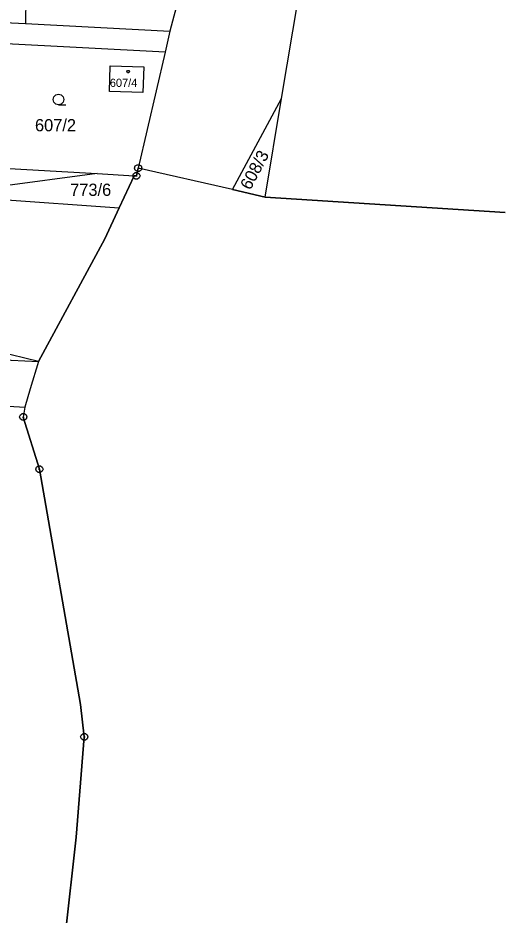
# Model space of a CAD drawing. Extents: x -759699 to -757730, y -1172308 to -1170857.
# Drawn here: x -758926.3 to -758859.4, y -1171766.9 to -1171642.4 of the extents above; entities that cross this region are included whole.
import ezdxf

# ---------------------------------------------------------------- set-up
doc = ezdxf.new("R2010")
doc.units = 0
for name, color, linetype in [('Vrstva 1', 7, 'Continuous'), ('Vrstva 11', 7, 'Continuous'), ('Vrstva 12', 7, 'Continuous'), ('Vrstva 2', 7, 'Continuous'), ('Vrstva 3', 7, 'Continuous'), ('Vrstva 5', 7, 'Continuous'), ('Vrstva 8', 7, 'Continuous')]:
    doc.layers.add(name, color=color, linetype=linetype)

msp = doc.modelspace()

# ---------------------------------------------------------------- linework, layer by layer
at = {"layer": 'Vrstva 1'}
for p, q in [((-758924.94, -1171622.09), (-758925.22, -1171643.14)), ((-758889.72, -1171653.54), (-758885.19, -1171626.24)), ((-758901.34, -1171629.35), (-758905.21, -1171644.2)), ((-758947.23, -1171641.98), (-758925.22, -1171643.14)), ((-758925.22, -1171643.14), (-758905.21, -1171644.2)), ((-758905.21, -1171644.2), (-758905.89, -1171647.12)), ((-758905.89, -1171647.12), (-758928.84, -1171645.89)), ((-758905.89, -1171647.12), (-758909.6, -1171663.2)), ((-758913.58, -1171652.56), (-758913.48, -1171648.99)), ((-758913.48, -1171648.99), (-758908.84, -1171649.12)), ((-758908.84, -1171649.12), (-758908.95, -1171652.69)), ((-758908.95, -1171652.69), (-758913.58, -1171652.56)), ((-758896.55, -1171666.17), (-758889.72, -1171653.54)), ((-758891.99, -1171667.21), (-758889.72, -1171653.54)), ((-758915.3, -1171663.96), (-758930.07, -1171665.92)), ((-758929.9, -1171663.12), (-758915.3, -1171663.96)), ((-758915.3, -1171663.96), (-758910.16, -1171664.25)), ((-758912.26, -1171668.73), (-758910.16, -1171664.25)), ((-758910.16, -1171664.25), (-758909.85, -1171664.27)), ((-758909.85, -1171664.27), (-758909.6, -1171663.2)), ((-758896.55, -1171666.17), (-758909.6, -1171663.2)), ((-758896.55, -1171666.17), (-758891.99, -1171667.21)), ((-758937.4, -1171666.9), (-758912.26, -1171668.73)), ((-758891.99, -1171667.21), (-758858.7, -1171669.36)), ((-758914.25, -1171672.99), (-758912.26, -1171668.73)), ((-758923.44, -1171690.05), (-758914.25, -1171672.99)), ((-758923.44, -1171690.05), (-758946.52, -1171684.31)), ((-759070.89, -1171687.29), (-758925.35, -1171696.39)), ((-758948.82, -1171688.7), (-758923.44, -1171690.05)), ((-758923.44, -1171690.05), (-758924.57, -1171693.81)), ((-758924.57, -1171693.81), (-758925.35, -1171696.39)), ((-758925.35, -1171696.39), (-758925.54, -1171697.74)), ((-758923.31, -1171704.98), (-758925.54, -1171697.74)), ((-758917.62, -1171737.66), (-758923.31, -1171704.98)), ((-758917.08, -1171742.13), (-758917.62, -1171737.66)), ((-758918.22, -1171756.06), (-758917.08, -1171742.13)), ((-758920.09, -1171772.69), (-758918.22, -1171756.06))]:
    msp.add_line(p, q, dxfattribs=at)
at = {"layer": 'Vrstva 11'}
for p, q in [((-758910.16, -1171664.25), (-758912.26, -1171668.73)), ((-758909.85, -1171664.27), (-758910.16, -1171664.25)), ((-758909.6, -1171663.2), (-758909.85, -1171664.27)), ((-758896.55, -1171666.17), (-758909.6, -1171663.2)), ((-758891.99, -1171667.21), (-758896.55, -1171666.17)), ((-758858.7, -1171669.36), (-758891.99, -1171667.21)), ((-758912.26, -1171668.73), (-758914.25, -1171672.99)), ((-758914.25, -1171672.99), (-758923.44, -1171690.05)), ((-758923.44, -1171690.05), (-758924.57, -1171693.81)), ((-758924.57, -1171693.81), (-758925.35, -1171696.39)), ((-758925.35, -1171696.39), (-758925.54, -1171697.74)), ((-758925.54, -1171697.74), (-758923.31, -1171704.98)), ((-758923.31, -1171704.98), (-758917.62, -1171737.66)), ((-758917.62, -1171737.66), (-758917.08, -1171742.13)), ((-758917.08, -1171742.13), (-758918.22, -1171756.06)), ((-758918.22, -1171756.06), (-758920.09, -1171772.69))]:
    msp.add_line(p, q, dxfattribs=at)
at = {"layer": 'Vrstva 12'}
for p, q in [((-758913.58, -1171652.56), (-758913.48, -1171648.99)), ((-758913.48, -1171648.99), (-758908.84, -1171649.12)), ((-758908.84, -1171649.12), (-758908.95, -1171652.69)), ((-758908.95, -1171652.69), (-758913.58, -1171652.56))]:
    msp.add_line(p, q, dxfattribs=at)
at = {"layer": 'Vrstva 3'}
msp.add_lwpolyline([(-758920.64, -1171654.41), (-758921.02, -1171654.31), (-758921.29, -1171654.04), (-758921.39, -1171653.67), (-758921.29, -1171653.3), (-758921.02, -1171653.03), (-758920.65, -1171652.93), (-758920.28, -1171653.03), (-758920.01, -1171653.3), (-758919.91, -1171653.68), (-758920.01, -1171654.06), (-758920.28, -1171654.33), (-758920.66, -1171654.43), (-758919.66, -1171654.43)], dxfattribs=at)
at = {"layer": 'Vrstva 5'}
msp.add_lwpolyline([(-758910.92, -1171649.66), (-758910.83, -1171649.81), (-758910.92, -1171649.96), (-758911.1, -1171649.96), (-758911.19, -1171649.81), (-758911.1, -1171649.66)], close=True, dxfattribs=at)
at = {"layer": 'Vrstva 8'}
for p, q in [((-758909.72, -1171663.2), (-758909.48, -1171663.2)), ((-758909.97, -1171664.27), (-758909.73, -1171664.27)), ((-758925.66, -1171697.74), (-758925.42, -1171697.74)), ((-758923.43, -1171704.98), (-758923.19, -1171704.98)), ((-758917.2, -1171742.13), (-758916.96, -1171742.13))]:
    msp.add_line(p, q, dxfattribs=at)
for points in [[(-758909.45, -1171662.72), (-758909.2, -1171662.9), (-758909.1, -1171663.19), (-758909.2, -1171663.48), (-758909.45, -1171663.66), (-758909.76, -1171663.66), (-758910.01, -1171663.48), (-758910.11, -1171663.19), (-758910.01, -1171662.9), (-758909.76, -1171662.72)], [(-758909.7, -1171663.79), (-758909.45, -1171663.97), (-758909.35, -1171664.26), (-758909.45, -1171664.55), (-758909.7, -1171664.73), (-758910.01, -1171664.73), (-758910.26, -1171664.55), (-758910.36, -1171664.26), (-758910.26, -1171663.97), (-758910.01, -1171663.79)], [(-758925.39, -1171697.26), (-758925.14, -1171697.44), (-758925.04, -1171697.73), (-758925.14, -1171698.02), (-758925.39, -1171698.2), (-758925.7, -1171698.2), (-758925.95, -1171698.02), (-758926.05, -1171697.73), (-758925.95, -1171697.44), (-758925.7, -1171697.26)], [(-758923.16, -1171704.5), (-758922.91, -1171704.68), (-758922.81, -1171704.97), (-758922.91, -1171705.26), (-758923.16, -1171705.44), (-758923.47, -1171705.44), (-758923.72, -1171705.26), (-758923.82, -1171704.97), (-758923.72, -1171704.68), (-758923.47, -1171704.5)], [(-758916.93, -1171741.65), (-758916.68, -1171741.83), (-758916.58, -1171742.12), (-758916.68, -1171742.41), (-758916.93, -1171742.59), (-758917.24, -1171742.59), (-758917.49, -1171742.41), (-758917.59, -1171742.12), (-758917.49, -1171741.83), (-758917.24, -1171741.65)]]:
    msp.add_lwpolyline(points, close=True, dxfattribs=at)

# ---------------------------------------------------------------- texts
at = {"layer": 'Vrstva 2'}
for s, height, p in [('607/4', 1.14, (-758913.543, -1171651.93)), ('607/2', 1.7, (-758923.923, -1171658.09)), ('773/6', 1.7, (-758919.04, -1171667.05))]:
    msp.add_text(s, height=height, dxfattribs=at).set_placement(p)
msp.add_text('608/3', height=1.7, rotation=62.10862, dxfattribs=at).set_placement((-758894.062, -1171666.349))

doc.saveas('drawing.dxf')
